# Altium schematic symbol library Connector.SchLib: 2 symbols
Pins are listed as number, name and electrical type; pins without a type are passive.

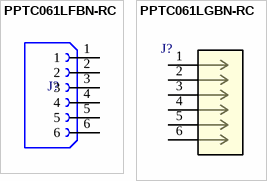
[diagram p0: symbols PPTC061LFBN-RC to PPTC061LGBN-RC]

## PPTC061LFBN-RC
designator J?  (value not drawn)
6 Position Header Connector 0.100" (2.54mm) Through Hole Tin; MF: Sullins Connector Solutions; MP: PPTC061LFBNRC
footprint PPTC061LFBN-RC (6 Position Header Connector 0.100" (2.54mm) Through Hole Tin)
pins: 1, 2, 3, 4, 5, 6

## PPTC061LGBN-RC
designator J?  (value not drawn)
6 Position Header Connector 0.100" (2.54mm) Through Hole, Right Angle Tin; Manufacturer_Name: Sullins
footprint PPTC061LGBN-RC (6 Position Header Connector 0.100" (2.54mm) Through Hole, Right Angle Tin)
pins: 1, 2, 3, 4, 5, 6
